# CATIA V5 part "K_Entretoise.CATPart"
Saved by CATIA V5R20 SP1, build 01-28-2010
Part number: entretoise
Publications: "trou_filetage"
Bounding box of the stored display mesh (mm): x -83.259 to -33.259, y 0 to 20, z -80.647 to -42.418
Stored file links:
  G:\Khaled_CFAO_2011\SIL\SIL_GR1\mroland\Khaled\CAD_CATIA_Modifie\K_Entretoise.CATPart
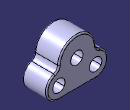
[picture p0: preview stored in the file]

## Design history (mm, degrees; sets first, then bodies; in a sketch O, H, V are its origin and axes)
Parameters
  LENGTH = 15 mm
  trou_filetage = 10 mm
  LENGTH = 0 mm
Set1
  Sketch1 on zx-plane, origin (0, 0, 0), H (-1, 0, 0), V (0, 0, 1)
    line L1 (43.2593, -80.6468) -> (73.2593, -80.6468)
    arc A1 centre (73.2593, -70.6468) radius 10 from (73.2593, -80.6468) to (72.9063, -60.6531) ccw
    point P3 (73.2593, -70.6468)
    arc A2 centre (58.2593, -57.4181) radius 15 from (72.9063, -60.6531) to (43.6123, -60.6531) ccw
    point P5 (58.2593, -57.4181)
    arc A3 centre (43.2593, -70.6468) radius 10 from (43.6123, -60.6531) to (43.2593, -80.6468) ccw
    point P7 (43.2593, -70.6468)
    radius A3 = 10
    radius A1 = 10
    radius A2 = 15
    distance P7 P3 = 30
    distance P3 P5 = 20
    distance P7 P5 = 20
    distance L1 H = 80.6468
    distance P5 V = 58.2593
    horizontal: L1 H
    tangency: A1 L1, L1 A3
Body1 (main body)
  Pad1: profile Sketch1, direction (0, 1, 0), length 20
  Fillet1: radius 5, on edge [face of Pad1 from Sketch1.A2 | face of Pad1 from Sketch1.A1]
  Fillet2: radius 5, on edge [face of Pad1 from Sketch1.A3 | face of Pad1 from Sketch1.A2]
  Fillet3: radius 1, on edge [face of Pad1 from Sketch1.A2 | end face of Pad1]
  Fillet4: radius 1, on edge [start face of Pad1 | face of Pad1 from Sketch1.A2]
  Sketch2 on end face of Pad1, origin (-59.2164, 20, -54.7715), H (1, 0, 0), V (0, 0, -1)
    point P1 (15.9571, 15.8753)
    reference projected point E1 (15.9571, 15.8753) from axis of face of Pad1 from Sketch1.A3
    distance P1 E1 = 0
  Hole1: placed by Sketch2, at (-43.2593, 20, -70.6468) direction (0, -1, 0), diameter 10, through (limit type 3)
  Sketch3 on end face of Pad1, origin (-64.6562, 20, -71.689), H (1, 0, 0), V (0, 0, -1)
    point P1 (-8.6031, -1.0421)
    reference projected point E1 (-8.6031, -1.0421) from axis of face of Pad1 from Sketch1.A1
    distance P1 E1 = 0
  Hole2: placed by Sketch3, at (-73.2593, 20, -70.6468) direction (0, -1, 0), diameter 10, through (limit type 3)
  Sketch4 on end face of Pad1, origin (-57.1001, 20, -52.6043), H (1, 0, 0), V (0, 0, -1)
    point P1 (-0.891, 5.7772)
    reference projected arc E1 centre (-1.1592, 4.8138) radius 14 from (-15.1443, 4.1692) to (12.826, 4.1692) ccw from edge [face of Fillet3 | end face of Pad1]
    radius E1 = 14 (reference)
  Hole3: placed by Sketch4, at (-57.9911, 20, -58.3815) direction (0, -1, 0), diameter 10 {= trou_filetage}, through (limit type 3)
